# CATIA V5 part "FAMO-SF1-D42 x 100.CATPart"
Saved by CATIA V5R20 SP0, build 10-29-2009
Part number: FAMO-SF1-D42 x 100
Definition: NONE
Nomenclature: FAMO-SF1-D42 x 100
Source: Unknown
Description: FAMO-SF1-D42 x 100
Bounding box of the stored display mesh (mm): x -53 to 47, y -31.5 to 31.5, z -31.5 to 31.5
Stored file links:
  C:\Users\Utente\Desktop\IO LAVORO\3D X SITO CF\X SITO\FAMO\FAMO-SF1-D42 x 100.CATPart
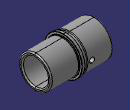
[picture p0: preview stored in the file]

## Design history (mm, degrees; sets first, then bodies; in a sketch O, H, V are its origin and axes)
Body1 "FAMO-SF1-D42 x 100" (main body)
  Solid1: solid without history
